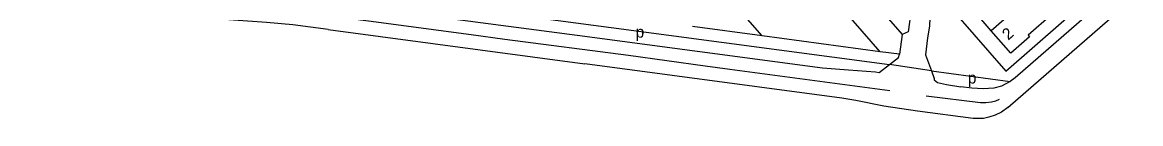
# Model space of a CAD drawing. Extents: x 155854 to 157362, y 383621 to 384685.
# Drawn here: x 156060.9 to 156451, y 383945.3 to 383977 of the extents above; entities that cross this region are included whole.
import ezdxf

# ---------------------------------------------------------------- set-up
doc = ezdxf.new("R2010")
doc.units = 0
for name, color, linetype in [('BLT_Basislijn', 7, 'Continuous'), ('BLT_Bebouwing', 7, 'Continuous'), ('BLT_Centroide', 7, 'Continuous'), ('BLT_Huisnummer', 7, 'Continuous'), ('BLT_Onderverdeling_panden', 7, 'Continuous'), ('BLT_Vlakafsluiter', 7, 'Continuous')]:
    doc.layers.add(name, color=color, linetype=linetype)

msp = doc.modelspace()

# ---------------------------------------------------------------- linework, layer by layer
at = {"layer": 'BLT_Basislijn'}
for p, q in [((156318.94, 383974.05), (156295.43, 384001)), ((156369.3, 384001.72), (156403.93, 383961.86)), ((156403.93, 383961.86), (156450.33, 384002.17)), ((156360.11, 383968.58), (156342.24, 383989.01)), ((156404.62, 383949.22), (156448.33, 383987.19)), ((156189.73, 383982.81), (156254.44, 383974.29)), ((156167.61, 383976.23), (156257.17, 383964.34)), ((156318.94, 383974.05), (156294.62, 383977.28)), ((156254.44, 383974.29), (156340.03, 383962.93)), ((156360.11, 383968.58), (156318.94, 383974.05)), ((156307.69, 383962.48), (156363.56, 383955.13)), ((156378.01, 383961.92), (156405.53, 383958.27))]:
    msp.add_line(p, q, dxfattribs=at)
for points in [[(156276.92, 384088.24), (156307.18, 384053.41), (156310.96, 384056.69), (156314.93, 384052.11), (156311.16, 384048.83), (156362.68, 383989.52), (156366.72, 383992.5), (156368.14, 383991.05), (156369.04, 383989.47), (156370.17, 383986.09), (156370.85, 383982.49), (156370.38, 383978.82), (156369.95, 383975.5), (156367.77, 383974.52)], [(156340.49, 384000.58), (156343.13, 384002.83), (156367.77, 383974.51)], [(156369.3, 384001.72), (156368.39, 383999.97), (156370.56, 383997.41), (156372.6, 383994.73), (156374.65, 383992.04), (156375.41, 383990.38), (156376.18, 383988.47), (156377.2, 383985.27), (156377.33, 383983.1), (156377.46, 383980.29), (156377.33, 383977.47), (156376.69, 383973.38), (156375.92, 383967.54), (156378.01, 383961.92)], [(156450.99, 383997.45), (156407.25, 383959.46), (156405.53, 383958.27)], [(156169.45, 383989.86), (156266.3, 383977), (156363.4, 383964.11)], [(156167.61, 383976.23), (156155.21, 383977.85), (156146.07, 383978.71), (156096.76, 383982.18), (156081.71, 383982.35), (156076.66, 383982.58), (156069.91, 383983.06), (156060.92, 383984.14)], [(156167.95, 383981.03), (156181.65, 383979.24), (156217.42, 383974.51), (156229.18, 383972.97)], [(156229.18, 383972.97), (156272.3, 383967.34), (156299.13, 383963.63), (156307.69, 383962.48)], [(156367.77, 383974.51), (156366.87, 383967.69), (156360.11, 383968.58)], [(156363.4, 383964.11), (156366.58, 383966.57), (156366.86, 383967.69)], [(156373.2, 383947.93), (156361.46, 383949.62), (156351.67, 383951.67), (156346.73, 383952.45), (156257.17, 383964.34)], [(156340.03, 383962.93), (156349.07, 383962.23), (156358.53, 383961.59), (156359.8, 383961.33), (156363.4, 383964.11)], [(156378.01, 383961.92), (156378.99, 383959.27), (156378.99, 383958.81), (156380.14, 383957.92), (156383.33, 383957.15), (156388.32, 383956.39)], [(156405.53, 383958.27), (156402.51, 383956.64), (156399.83, 383955.87), (156396.12, 383955.62), (156392.16, 383955.87), (156388.32, 383956.39)], [(156376.17, 383953.22), (156395.19, 383950.97), (156396.94, 383950.97), (156398.93, 383951.13), (156400.52, 383951.52), (156401.77, 383952.11)], [(156404.62, 383949.22), (156402.51, 383947.62), (156400.2, 383946.51), (156398.05, 383945.8), (156396.22, 383945.4), (156394.16, 383945.32), (156392.57, 383945.4), (156373.2, 383947.93)]]:
    msp.add_lwpolyline(points, dxfattribs=at)
at = {"layer": 'BLT_Bebouwing'}
msp.add_line((156398.91, 383975.78), (156394.65, 383980.69), dxfattribs=at)
msp.add_lwpolyline([(156420.01, 383981.46), (156411.81, 383974.27), (156412.21, 383973.69), (156405.71, 383968.07), (156398.91, 383975.78)], dxfattribs=at)
at = {"layer": 'BLT_Onderverdeling_panden'}
msp.add_line((156407.74, 383983.45), (156398.91, 383975.78), dxfattribs=at)
at = {"layer": 'BLT_Vlakafsluiter'}
msp.add_line((156378.01, 383961.92), (156363.4, 383964.11), dxfattribs=at)

# ---------------------------------------------------------------- texts
at = {"layer": 'BLT_Centroide'}
for p in [(156274.86, 383973.45), (156390.72, 383957.52)]:
    msp.add_text('p', height=4, dxfattribs=at).set_placement(p)
at = {"layer": 'BLT_Huisnummer'}
msp.add_text('2', height=4, rotation=40.9824, dxfattribs=at).set_placement((156404.81, 383972.38))

doc.saveas('drawing.dxf')
